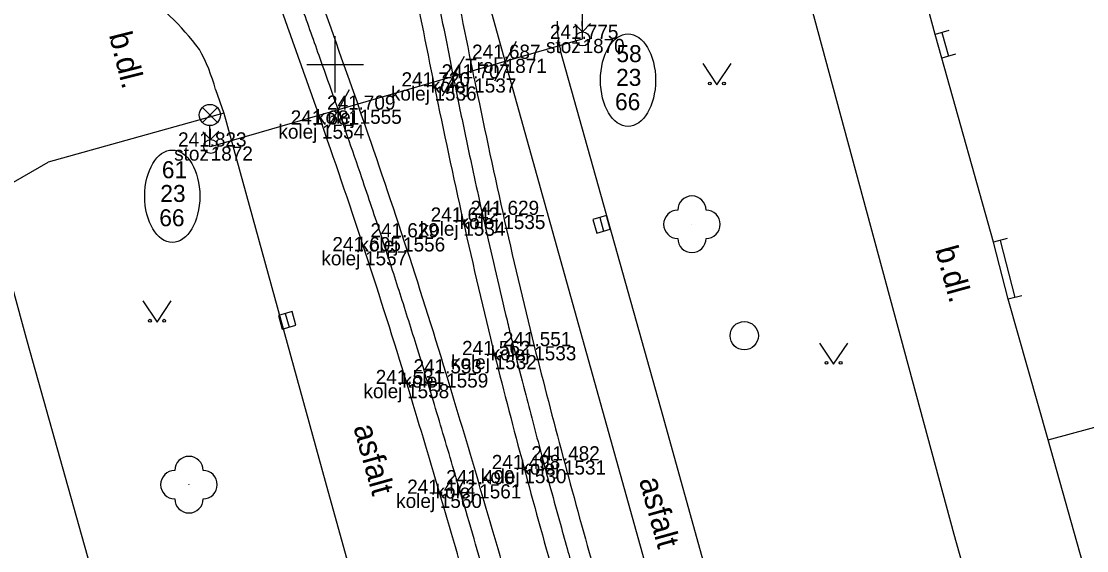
# Model space of a CAD drawing. Extents: x -599098 to -598820, y -1159597 to -1158744.
# Drawn here: x -599061.09 to -599023.45, y -1158817.18 to -1158798.48 of the extents above; entities that cross this region are included whole.
import ezdxf

# ---------------------------------------------------------------- set-up
doc = ezdxf.new("R2010")
doc.units = 0
for name, color, linetype in [('body', 7, 'Continuous'), ('budovy', 7, 'Continuous'), ('dopravní značky semafory', 7, 'Continuous'), ('druh pozemku stromy', 7, 'Continuous'), ('hektometrická síť', 7, 'Continuous'), ('kresba', 7, 'Continuous'), ('kódy bodů', 7, 'Continuous'), ('popisy', 7, 'Continuous'), ('tram_koleje', 7, 'Continuous'), ('tram_osa', 7, 'Continuous'), ('trol_detaily', 7, 'Continuous'), ('trol_převěsy', 7, 'Continuous'), ('trol_troljová stopa', 7, 'Continuous'), ('trol_ved sloupy konzoly', 7, 'Continuous'), ('trol_čísla sloupů', 7, 'Continuous'), ('výšky bodů', 7, 'Continuous'), ('značky IS', 7, 'Continuous'), ('čísla bodů', 7, 'Continuous')]:
    doc.layers.add(name, color=color, linetype=linetype)

msp = doc.modelspace()

# ---------------------------------------------------------------- linework, layer by layer
at = {"layer": 'body'}
for p, q in [((-599041.262, -1158799.101), (-599041.262, -1158799.101)), ((-599044.013, -1158799.804), (-599044.013, -1158799.804)), ((-599045.09, -1158800.499), (-599045.09, -1158800.499)), ((-599046.492, -1158800.781), (-599046.492, -1158800.781)), ((-599049.138, -1158801.601), (-599049.138, -1158801.601)), ((-599050.466, -1158802.126), (-599050.466, -1158802.126)), ((-599054.399, -1158802.902), (-599054.399, -1158802.902)), ((-599044.063, -1158805.318), (-599044.063, -1158805.318)), ((-599045.476, -1158805.555), (-599045.476, -1158805.555)), ((-599047.604, -1158806.111), (-599047.604, -1158806.111)), ((-599048.947, -1158806.6), (-599048.947, -1158806.6)), ((-599042.97, -1158809.955), (-599042.97, -1158809.955)), ((-599044.368, -1158810.268), (-599044.368, -1158810.268)), ((-599046.082, -1158810.917), (-599046.082, -1158810.917)), ((-599047.462, -1158811.292), (-599047.462, -1158811.292)), ((-599041.921, -1158813.989), (-599041.921, -1158813.989)), ((-599043.318, -1158814.296), (-599043.318, -1158814.296)), ((-599044.915, -1158814.833), (-599044.915, -1158814.833)), ((-599046.306, -1158815.169), (-599046.306, -1158815.169))]:
    msp.add_line(p, q, dxfattribs=at)
at = {"layer": 'budovy'}
for p, q in [((-599028.81, -1158798.94), (-599029.62, -1158795.96)), ((-599028.57, -1158799.78), (-599028.81, -1158798.94)), ((-599026.75, -1158806.28), (-599028.57, -1158799.78)), ((-599026.23, -1158808.3), (-599026.75, -1158806.28)), ((-599024.82, -1158813.26), (-599026.23, -1158808.3)), ((-599024.82, -1158813.26), (-599018.089, -1158811.461)), ((-599023.48, -1158818), (-599024.82, -1158813.26))]:
    msp.add_line(p, q, dxfattribs=at)
at = {"layer": 'dopravní značky semafory'}
msp.add_line((-599041.262, -1158799.101), (-599041.262, -1158798.101), dxfattribs=at)
at = {"layer": 'druh pozemku stromy'}
for points in [[(-599037.018, -1158799.976), (-599036.518, -1158800.726), (-599036.018, -1158799.976)], [(-599056.795, -1158808.355), (-599056.295, -1158809.105), (-599055.795, -1158808.355)], [(-599032.897, -1158809.846), (-599032.397, -1158810.596), (-599031.897, -1158809.846)]]:
    msp.add_lwpolyline(points, dxfattribs=at)
for centre, radius in [((-599036.768, -1158800.676), 0.05), ((-599036.268, -1158800.676), 0.05), ((-599037.4, -1158805.65), 0.0005), ((-599056.545, -1158809.055), 0.05), ((-599056.045, -1158809.055), 0.05), ((-599032.647, -1158810.546), 0.05), ((-599032.147, -1158810.546), 0.05), ((-599055.167, -1158814.847), 0.0005)]:
    msp.add_circle(centre, radius, dxfattribs=at)
for centre, start, end in [((-599037.4, -1158805.15), 0, 180), ((-599037.9, -1158805.65), 90, 270), ((-599036.9, -1158805.65), 270, 90), ((-599037.4, -1158806.15), 180, 360), ((-599055.167, -1158814.347), 0, 180), ((-599055.667, -1158814.847), 90, 270), ((-599054.667, -1158814.847), 270, 90), ((-599055.167, -1158815.347), 180, 360)]:
    msp.add_arc(centre, 0.5, start, end, dxfattribs=at)
at = {"layer": 'hektometrická síť'}
for p, q in [((-599050, -1158801), (-599050, -1158799)), ((-599051, -1158800), (-599049, -1158800))]:
    msp.add_line(p, q, dxfattribs=at)
at = {"layer": 'kresba'}
for p, q in [((-599028.14, -1158816.61), (-599033.21, -1158797.85)), ((-599028.329, -1158798.803), (-599028.81, -1158798.94)), ((-599028.57, -1158798.871), (-599028.33, -1158799.711)), ((-599038.5, -1158812.15), (-599042.04, -1158799.52)), ((-599028.089, -1158799.643), (-599028.57, -1158799.78)), ((-599054.23, -1158800.89), (-599053.94, -1158801.73)), ((-599053.94, -1158801.73), (-599060.14, -1158803.45)), ((-599053.94, -1158801.73), (-599050.36, -1158814.72)), ((-599061.37, -1158804.16), (-599060.139, -1158803.454)), ((-599060.87, -1158809.81), (-599061.93, -1158805.96)), ((-599026.266, -1158806.155), (-599026.75, -1158806.28)), ((-599026.508, -1158806.218), (-599025.988, -1158808.238)), ((-599025.746, -1158808.175), (-599026.23, -1158808.3)), ((-599052.85, -1158838.43), (-599060.87, -1158809.81)), ((-599034.9, -1158825.08), (-599038.5, -1158812.15)), ((-599050.36, -1158814.72), (-599046.59, -1158828.27)), ((-599024.24, -1158830.05), (-599028.14, -1158816.61))]:
    msp.add_line(p, q, dxfattribs=at)
for centre, radius, start, end in [((-599062.719, -1158805.456), 9.927, 37.0843, 55.2434), ((-599038.178, -1158798.547), 3.982, 179.0288, 194.1351), ((-599060.224, -1158802.472), 6.2, 14.7823, 28.9596)]:
    msp.add_arc(centre, radius, start, end, dxfattribs=at)
at = {"layer": 'tram_koleje'}
for centre, radius, start, end in [((-599536.84, -1158897.01), 501.131, 11.10372, 12.14061), ((-599529.595, -1158895.69), 492.338, 11.11461, 12.15891), ((-597210.712, -1158150.292), 1950.388, 199.246436, 199.507983), ((-597789.976, -1158353.746), 1337.864, 199.196739, 199.581422), ((-598824.298, -1158755.964), 225.239, 191.40389, 193.86919), ((-598821.824, -1158755.462), 229.194, 191.40431, 193.83485), ((-599267.683, -1158878.451), 231.664, 16.94892, 19.37397), ((-599269.435, -1158878.965), 232.059, 16.95482, 19.33652), ((-598778.54, -1158743.346), 272.69, 194.13845, 195.82811), ((-598780.621, -1158743.667), 272.026, 194.17207, 195.876), ((-599584.712, -1158973.565), 562.652, 15.99198, 16.80254), ((-599586.761, -1158974.205), 563.369, 15.99466, 16.80866)]:
    msp.add_arc(centre, radius, start, end, dxfattribs=at)
at = {"layer": 'tram_osa'}
for points in [[(-599050.226, -1158781.191), (-599049.779, -1158782.843), (-599049.26, -1158784.839), (-599048.908, -1158786.239), (-599048.459, -1158788.087), (-599047.812, -1158790.885), (-599047.609, -1158791.804), (-599047.116, -1158794.12), (-599046.807, -1158795.602), (-599046.534, -1158796.929), (-599046.277, -1158798.195), (-599045.991, -1158799.626), (-599045.791, -1158800.64), (-599045.594, -1158801.602), (-599045.202, -1158803.462), (-599044.904, -1158804.829), (-599044.69, -1158805.788), (-599044.317, -1158807.41), (-599043.931, -1158809.037), (-599043.782, -1158809.649), (-599043.669, -1158810.111), (-599043.304, -1158811.541), (-599043.022, -1158812.624), (-599042.724, -1158813.749), (-599042.438, -1158814.813), (-599042.08, -1158816.121), (-599041.806, -1158817.102), (-599041.581, -1158817.902)], [(-599044.518, -1158818.761), (-599044.868, -1158817.544), (-599045.327, -1158815.967), (-599045.725, -1158814.611), (-599046.408, -1158812.312), (-599046.772, -1158811.104), (-599047.143, -1158809.897), (-599047.745, -1158807.988), (-599048.359, -1158806.1), (-599049.061, -1158804.005), (-599049.575, -1158802.512), (-599050.57, -1158799.693), (-599051.212, -1158797.872), (-599051.881, -1158795.968), (-599052.492, -1158794.222), (-599053.195, -1158792.184), (-599053.706, -1158790.656), (-599054.07, -1158789.541), (-599054.412, -1158788.474), (-599055.062, -1158786.382), (-599055.575, -1158784.668), (-599055.829, -1158783.8), (-599056.112, -1158782.812)]]:
    msp.add_spline(points, degree=3, dxfattribs=at)
at = {"layer": 'trol_detaily'}
for p, q in [((-599043.606, -1158799.19), (-599044.376, -1158800.591)), ((-599045.448, -1158799.723), (-599046.219, -1158801.125)), ((-599049.512, -1158800.899), (-599050.282, -1158802.3))]:
    msp.add_line(p, q, dxfattribs=at)
at = {"layer": 'trol_převěsy'}
msp.add_line((-599054.399, -1158802.902), (-599041.262, -1158799.101), dxfattribs=at)
at = {"layer": 'trol_troljová stopa'}
for p, q in [((-599043.991, -1158799.891), (-599045.552, -1158794.297)), ((-599038.311, -1158820.248), (-599043.991, -1158799.891))]:
    msp.add_line(p, q, dxfattribs=at)
at = {"layer": 'trol_ved sloupy konzoly'}
for p, q in [((-599041.265, -1158798.852), (-599041.54, -1158798.585)), ((-599041.265, -1158798.852), (-599041.271, -1158798.48)), ((-599041.265, -1158798.852), (-599040.979, -1158798.559)), ((-599054.402, -1158802.653), (-599054.677, -1158802.386)), ((-599054.402, -1158802.653), (-599054.408, -1158802.281)), ((-599054.402, -1158802.653), (-599054.116, -1158802.36))]:
    msp.add_line(p, q, dxfattribs=at)
for centre in [(-599041.261, -1158799.102), (-599054.398, -1158802.903)]:
    msp.add_circle(centre, 0.248, dxfattribs=at)
at = {"layer": 'trol_čísla sloupů'}
for centre in [(-599039.657, -1158800.559), (-599055.757, -1158804.659)]:
    msp.add_ellipse(centre, major_axis=(0, -1.633), ratio=0.595913, dxfattribs=at)
at = {"layer": 'značky IS'}
for p, q in [((-599054.693, -1158802.052), (-599054.165, -1158801.524)), ((-599054.157, -1158802.05), (-599054.685, -1158801.52)), ((-599054.429, -1158802.914), (-599054.429, -1158802.164)), ((-599040.658, -1158805.409), (-599040.522, -1158805.891)), ((-599051.768, -1158808.799), (-599051.632, -1158809.281))]:
    msp.add_line(p, q, dxfattribs=at)
for points in [[(-599040.899, -1158805.478), (-599040.764, -1158805.959), (-599040.282, -1158805.823), (-599040.417, -1158805.342)], [(-599052.009, -1158808.868), (-599051.874, -1158809.349), (-599051.392, -1158809.213), (-599051.527, -1158808.732)]]:
    msp.add_lwpolyline(points, close=True, dxfattribs=at)
for centre, radius in [((-599054.429, -1158801.789), 0.375), ((-599035.552, -1158809.586), 0.5)]:
    msp.add_circle(centre, radius, dxfattribs=at)

# ---------------------------------------------------------------- texts
at = {"layer": 'kódy bodů'}
for s, p in [('stoz', (-599042.552, -1158799.601)), ('Trol', (-599045.413, -1158800.304)), ('kolej', (-599046.63, -1158800.999)), ('kolej', (-599048.032, -1158801.281)), ('kolej', (-599050.678, -1158802.101)), ('kolej', (-599052.006, -1158802.626)), ('stoz', (-599055.689, -1158803.402)), ('kolej', (-599045.603, -1158805.818)), ('kolej', (-599047.016, -1158806.055)), ('kolej', (-599049.144, -1158806.611)), ('kolej', (-599050.487, -1158807.1)), ('kolej', (-599044.51, -1158810.455)), ('kolej', (-599045.908, -1158810.768)), ('kolej', (-599047.622, -1158811.417)), ('kolej', (-599049.002, -1158811.792)), ('kolej', (-599043.461, -1158814.489)), ('kolej', (-599044.858, -1158814.796)), ('kolej', (-599046.455, -1158815.333)), ('kolej', (-599047.846, -1158815.669))]:
    msp.add_text(s, height=0.5, dxfattribs=at).set_placement(p)
at = {"layer": 'popisy'}
for s, rotation, p in [('b.dl.', 284.1309, (-599057.997, -1158798.957)), ('b.dl.', 285.3605, (-599028.81, -1158806.528)), ('asfalt', 285.5601, (-599049.363, -1158812.817)), ('asfalt', 285.5601, (-599039.275, -1158814.688))]:
    msp.add_text(s, height=0.8, rotation=rotation, dxfattribs=at).set_placement(p)
at = {"layer": 'trol_čísla sloupů'}
for s, p in [('58', (-599040.066, -1158799.922)), ('23', (-599040.079, -1158800.76)), ('66', (-599040.116, -1158801.619)), ('61', (-599056.124, -1158804.022)), ('23', (-599056.179, -1158804.86)), ('66', (-599056.216, -1158805.719))]:
    msp.add_text(s, height=0.6, dxfattribs=at).set_placement(p)
at = {"layer": 'výšky bodů'}
for s, p in [('241.775', (-599042.414, -1158799.101)), ('241.687', (-599045.165, -1158799.804)), ('241.707', (-599046.242, -1158800.499)), ('241.720', (-599047.658, -1158800.781)), ('241.709', (-599050.29, -1158801.601)), ('241.681', (-599051.574, -1158802.126)), ('241.823', (-599055.551, -1158802.902)), ('241.642', (-599046.628, -1158805.555)), ('241.629', (-599045.215, -1158805.318)), ('241.629', (-599048.756, -1158806.111)), ('241.605', (-599050.099, -1158806.6)), ('241.551', (-599044.078, -1158809.955)), ('241.562', (-599045.52, -1158810.268)), ('241.553', (-599047.234, -1158810.917)), ('241.531', (-599048.57, -1158811.292)), ('241.482', (-599043.073, -1158813.989)), ('241.498', (-599044.47, -1158814.296)), ('241.490', (-599046.081, -1158814.833)), ('241.472', (-599047.458, -1158815.169))]:
    msp.add_text(s, height=0.5, dxfattribs=at).set_placement(p)
at = {"layer": 'čísla bodů'}
for s, p in [('1870', (-599041.262, -1158799.601)), ('1871', (-599044.013, -1158800.304)), ('1537', (-599045.09, -1158800.999)), ('1536', (-599046.492, -1158801.281)), ('1555', (-599049.138, -1158802.101)), ('1554', (-599050.466, -1158802.626)), ('1872', (-599054.399, -1158803.402)), ('1535', (-599044.063, -1158805.818)), ('1534', (-599045.476, -1158806.055)), ('1556', (-599047.604, -1158806.611)), ('1557', (-599048.947, -1158807.1)), ('1533', (-599042.97, -1158810.455)), ('1532', (-599044.368, -1158810.768)), ('1559', (-599046.082, -1158811.417)), ('1558', (-599047.462, -1158811.792)), ('1531', (-599041.921, -1158814.489)), ('1530', (-599043.318, -1158814.796)), ('1561', (-599044.915, -1158815.333)), ('1560', (-599046.306, -1158815.669))]:
    msp.add_text(s, height=0.5, dxfattribs=at).set_placement(p)

doc.saveas('drawing.dxf')
